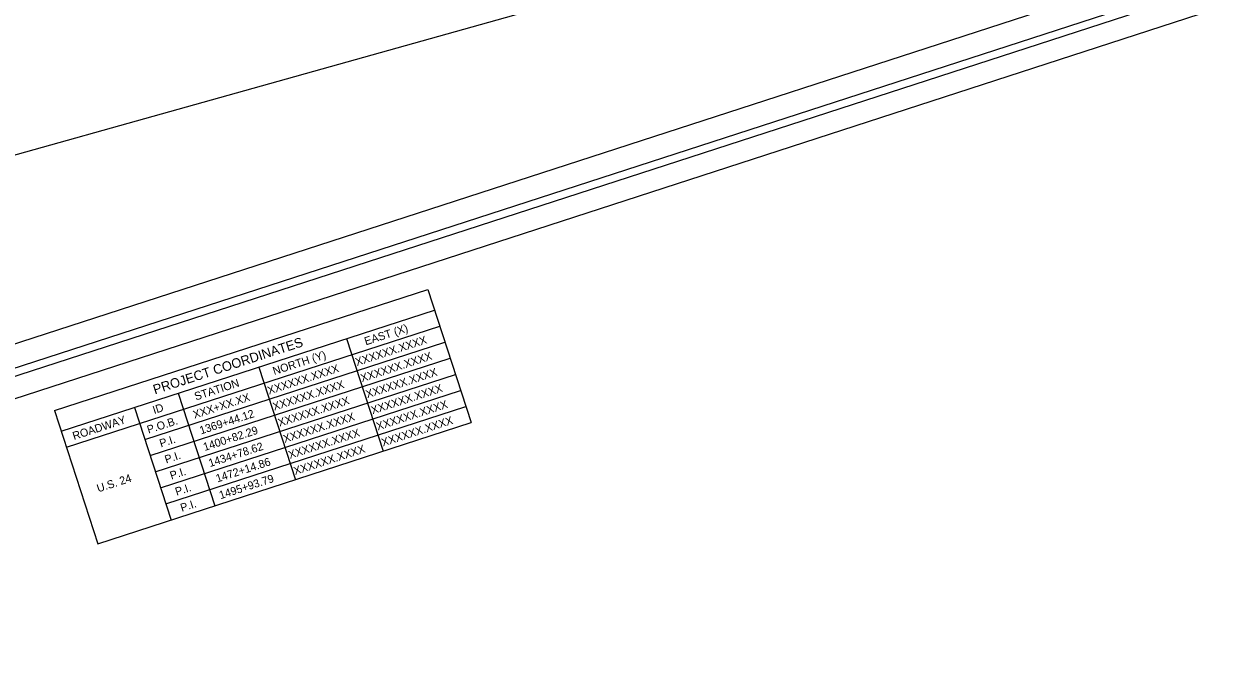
# Model space of a CAD drawing. Extents: x -468556195 to 3353078, y -306091294 to 1252632.
# Drawn here: x 1831176 to 1836968, y 529645 to 532729 of the extents above; entities that cross this region are included whole.
import ezdxf

# ---------------------------------------------------------------- set-up
doc = ezdxf.new("R2010")
doc.units = 0
for name, color, linetype in [('Level 40', 7, 'Continuous'), ('Level 63', 7, 'Continuous'), ('SC_Scratch1', 7, 'Continuous'), ('SH_Border', 7, 'Continuous'), ('SH_Cut_Line', 7, 'Continuous')]:
    doc.layers.add(name, color=color, linetype=linetype)

msp = doc.modelspace()

# ---------------------------------------------------------------- linework, layer by layer
at = {"layer": 'Level 40'}
for p, q in [((1831325.9, 530842.5), (1833144.9, 531433.1)), ((1833144.9, 531433.1), (1833355.7, 530784)), ((1831358.3, 530742.7), (1833177.4, 531333.2)), ((1831383.8, 530664.2), (1833202.8, 531254.8)), ((1831766, 530701.5), (1833228.3, 531176.3)), ((1832749.4, 531194.3), (1832927.7, 530645)), ((1831791.4, 530623.1), (1833253.8, 531097.8)), ((1832321.4, 531055.3), (1832499.7, 530506)), ((1831816.9, 530544.6), (1833279.3, 531019.4)), ((1831842.4, 530466.1), (1833304.7, 530940.9)), ((1831929, 530927.9), (1832107.3, 530378.7)), ((1831325.9, 530842.5), (1831536.7, 530193.4)), ((1831715, 530858.5), (1831893.3, 530309.2)), ((1831867.9, 530387.7), (1833330.2, 530862.4)), ((1831536.7, 530193.4), (1833355.7, 530784))]:
    msp.add_line(p, q, dxfattribs=at)
at = {"layer": 'Level 63'}
for points in [[(1825229.4, 535921.9), (1834930.2, 539071.3), (1836968, 532794.6), (1827267.2, 529645.1)], [(1827336.2, 529818.9), (1836809.4, 532894.5), (1834849.2, 538932.3), (1825375.9, 535856.7)]]:
    msp.add_lwpolyline(points, close=True, dxfattribs=at)
at = {"layer": 'SC_Scratch1'}
msp.add_lwpolyline([(1826839.3, 533890.1), (1826769.8, 534863.1), (1833950.4, 537284.3), (1834448.3, 536360.7), (1835055.9, 534489.2), (1835128.1, 533209.3), (1827818.5, 531160.4), (1827446.8, 532019.1)], close=True, dxfattribs=at)
at = {"layer": 'SH_Border'}
msp.add_lwpolyline([(1825526.9, 535973.1), (1834657.8, 538937.5), (1836603.1, 532945.4), (1827472.3, 529981)], close=True, dxfattribs=at)
at = {"layer": 'SH_Cut_Line'}
msp.add_lwpolyline([(1827090.6, 529699.4), (1836792.1, 532849), (1834754.1, 539126.5), (1825052.6, 535976.8)], close=True, dxfattribs=at)

# ---------------------------------------------------------------- texts
at = {"layer": 'Level 40'}
for s, height, p in [('EAST (X)', 39, (1832842.9, 531160.8)), ('PROJECT COORDINATES', 46.5, (1831814.8, 530921.6)), ('XXXXXX.XXXX', 39, (1832799.1, 531059.8)), ('NORTH (Y)', 39, (1832396.5, 531015.9)), ('XXXXXX.XXXX', 39, (1832824.5, 530981.3)), ('XXXXXX.XXXX', 39, (1832371, 530920.8)), ('XXXXXX.XXXX', 39, (1832850, 530902.9)), ('STATION', 39, (1832014.6, 530891.8)), ('XXXXXX.XXXX', 39, (1832396.5, 530842.4)), ('XXX+XX.XX', 39, (1832007.8, 530802.9)), ('XXXXXX.XXXX', 39, (1832875.5, 530824.4)), ('ID', 39, (1831811.3, 530825.8)), ('XXXXXX.XXXX', 39, (1832422, 530763.9)), ('XXXXXX.XXXX', 39, (1832901, 530745.9)), ('ROADWAY', 39, (1831420.8, 530699.1)), ('P.O.B.', 39, (1831783.7, 530730.2)), ('1369+44.12', 39, (1832039.4, 530726.4)), ('XXXXXX.XXXX', 39, (1832447.5, 530685.4)), ('XXXXXX.XXXX', 39, (1832926.4, 530667.5)), ('1400+82.29', 39, (1832057.5, 530645.6)), ('XXXXXX.XXXX', 39, (1832472.9, 530607)), ('P.I.', 39, (1831844.4, 530663.1)), ('P.I.', 39, (1831869.9, 530584.7)), ('1434+78.62', 39, (1832083.3, 530567.2)), ('XXXXXX.XXXX', 39, (1832498.4, 530528.5)), ('1472+14.86', 39, (1832119.1, 530492.1)), ('U.S. 24', 39, (1831539, 530443.8)), ('P.I.', 39, (1831895.4, 530506.2)), ('1495+93.79', 39, (1832135, 530410.5)), ('P.I.', 39, (1831920.8, 530427.7)), ('P.I.', 39, (1831946.3, 530349.2))]:
    msp.add_text(s, height=height, rotation=17.9864, dxfattribs=at).set_placement(p)

doc.saveas('drawing.dxf')
